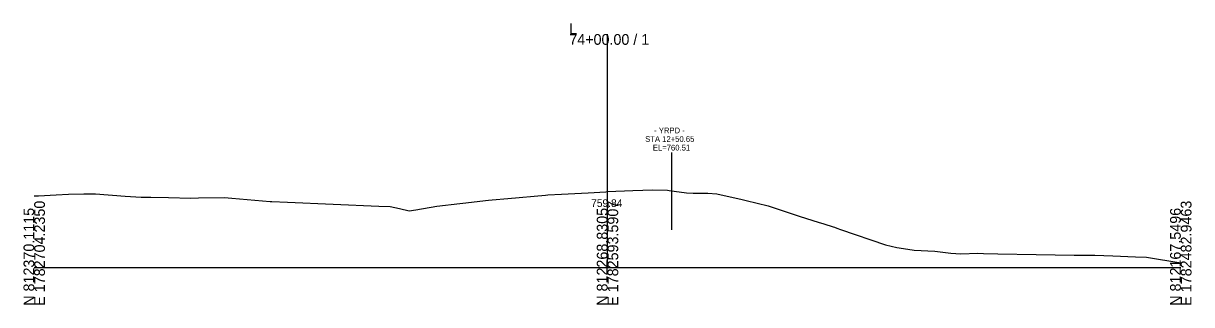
# Model space of a CAD drawing. Extents: x -26 to 7903, y -10 to 9573.
# Drawn here: x 3997.2 to 4302.8, y 4990.3 to 5063.8 of the extents above; entities that cross this region are included whole.
import ezdxf

# ---------------------------------------------------------------- set-up
doc = ezdxf.new("R2010")
doc.units = 0
for name, color, linetype in [('Exist Cross Section Cell', 7, 'Continuous'), ('Exist XS Center Line Elevation Label', 7, 'Continuous'), ('Exist XS Ground Line', 7, 'Continuous'), ('Prop XS Vertical Lines Alignments', 7, 'Continuous')]:
    doc.layers.add(name, color=color, linetype=linetype)

msp = doc.modelspace()

# ---------------------------------------------------------------- linework, layer by layer
at = {"layer": 'Exist Cross Section Cell'}
for p, q in [((4150, 5000), (4150, 5061.04)), ((4000, 5000), (4150, 5000)), ((4150, 5000), (4300, 5000))]:
    msp.add_line(p, q, dxfattribs=at)
at = {"layer": 'Exist XS Ground Line'}
for p, q in [((4137.97, 5019.2), (4144.98, 5019.57)), ((4144.98, 5019.57), (4149.55, 5019.82)), ((4149.55, 5019.82), (4150, 5019.84)), ((4150, 5019.84), (4156.59, 5020.12)), ((4156.59, 5020.12), (4161.83, 5020.35)), ((4161.83, 5020.35), (4165.69, 5020.25)), ((4165.69, 5020.25), (4166.14, 5020.18)), ((4166.14, 5020.18), (4170.65, 5019.57)), ((4170.65, 5019.57), (4172.43, 5019.49)), ((4172.43, 5019.49), (4176.23, 5019.42)), ((4176.23, 5019.42), (4178.63, 5019.25)), ((4000, 5018.72), (4001.1, 5018.76)), ((4001.1, 5018.76), (4005.75, 5019)), ((4005.75, 5019), (4009.01, 5019.19)), ((4009.01, 5019.19), (4013, 5019.25)), ((4013, 5019.25), (4016.01, 5019.25)), ((4016.01, 5019.25), (4023.81, 5018.64)), ((4023.81, 5018.64), (4027.96, 5018.36)), ((4027.96, 5018.36), (4030.52, 5018.42)), ((4030.52, 5018.42), (4035.16, 5018.29)), ((4035.16, 5018.29), (4040.95, 5018.13)), ((4040.95, 5018.13), (4042.94, 5018.2)), ((4042.94, 5018.2), (4049.81, 5018.28)), ((4049.81, 5018.28), (4051.72, 5018.13)), ((4051.72, 5018.13), (4061.74, 5017.29)), ((4061.74, 5017.29), (4062.18, 5017.28)), ((4062.18, 5017.28), (4066.29, 5017.1)), ((4066.29, 5017.1), (4090.2, 5016.08)), ((4105.38, 5016.06), (4111.36, 5016.72)), ((4111.36, 5016.72), (4112.18, 5016.84)), ((4112.18, 5016.84), (4118.86, 5017.58)), ((4118.86, 5017.58), (4119.86, 5017.7)), ((4119.86, 5017.7), (4123.96, 5018.06)), ((4123.96, 5018.06), (4133.79, 5018.94)), ((4133.79, 5018.94), (4134.41, 5018.98)), ((4134.41, 5018.98), (4137.97, 5019.2)), ((4178.63, 5019.25), (4185.27, 5017.82)), ((4185.27, 5017.82), (4186.32, 5017.57)), ((4186.32, 5017.57), (4192.04, 5016.12)), ((4090.2, 5016.08), (4093.11, 5015.99)), ((4093.11, 5015.99), (4095.54, 5015.44)), ((4095.54, 5015.44), (4098.1, 5014.82)), ((4098.1, 5014.82), (4099.85, 5015.1)), ((4099.85, 5015.1), (4105.38, 5016.06)), ((4192.04, 5016.12), (4200.44, 5013.33)), ((4200.44, 5013.33), (4205.08, 5011.86)), ((4205.08, 5011.86), (4206.62, 5011.39)), ((4206.62, 5011.39), (4209.02, 5010.65)), ((4209.02, 5010.65), (4209.36, 5010.54)), ((4209.36, 5010.54), (4210.03, 5010.3)), ((4210.03, 5010.3), (4210.99, 5009.98)), ((4210.99, 5009.98), (4222.73, 5005.93)), ((4222.73, 5005.93), (4225.73, 5005.26)), ((4225.73, 5005.26), (4228.58, 5004.77)), ((4228.58, 5004.77), (4230.27, 5004.56)), ((4230.27, 5004.56), (4235.62, 5004.24)), ((4235.62, 5004.24), (4239.87, 5003.74)), ((4239.87, 5003.74), (4242.48, 5003.61)), ((4242.48, 5003.61), (4246.94, 5003.74)), ((4246.94, 5003.74), (4248.39, 5003.67)), ((4248.39, 5003.67), (4252.09, 5003.62)), ((4252.09, 5003.62), (4262.17, 5003.4)), ((4262.17, 5003.4), (4272.14, 5003.25)), ((4272.14, 5003.25), (4277.51, 5003.21)), ((4277.51, 5003.21), (4282.19, 5003.02)), ((4282.19, 5003.02), (4288.16, 5002.81)), ((4288.16, 5002.81), (4291.05, 5002.68)), ((4291.05, 5002.68), (4300, 5001.25))]:
    msp.add_line(p, q, dxfattribs=at)
at = {"layer": 'Prop XS Vertical Lines Alignments'}
msp.add_line((4166.78, 5030.1), (4166.78, 5009.84), dxfattribs=at)

# ---------------------------------------------------------------- texts
at = {"layer": 'Exist Cross Section Cell'}
for s, p in [('L', (4140, 5061.04)), ('74+00.00 / 1', (4140, 5058.24))]:
    msp.add_text(s, height=2.8, dxfattribs=at).set_placement(p)
for s, p in [('E 1782704.2350', (4002.8, 4990)), ('E 1782593.5907', (4152.8, 4990)), ('E 1782482.9463', (4302.8, 4990)), ('N 812370.1115', (4000, 4990)), ('N 812268.8305', (4150, 4990)), ('N 812167.5496', (4300, 4990))]:
    msp.add_text(s, height=2.8, rotation=90, dxfattribs=at).set_placement(p)
at = {"layer": 'Exist XS Center Line Elevation Label'}
msp.add_text('759.84', height=2, dxfattribs=at).set_placement((4145.72, 5015.84))
at = {"layer": 'Prop XS Vertical Lines Alignments'}
for s, p in [('- YRPD -', (4162.2, 5035.1)), ('STA 12+50.65', (4159.85, 5032.85)), ('EL=760.51', (4161.87, 5030.6))]:
    msp.add_text(s, height=1.5, dxfattribs=at).set_placement(p)

doc.saveas('drawing.dxf')
